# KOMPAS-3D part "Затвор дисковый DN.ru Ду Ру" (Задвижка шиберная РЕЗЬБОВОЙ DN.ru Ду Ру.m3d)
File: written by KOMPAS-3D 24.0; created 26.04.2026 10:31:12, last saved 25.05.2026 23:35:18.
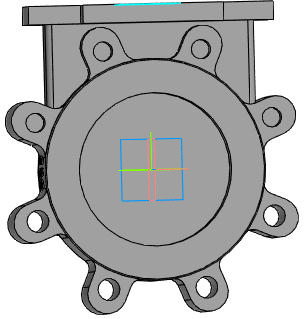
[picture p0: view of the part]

Document properties: Автор: R2D2; Полное имя файла: E:\Работа\Зайцев\GVKR1331M-1W-Fb-2P Задвижка шиберная с выдвижным штоком DN.ru Ду50-300 Ру16-10-6 с пневмоприводом\исходные материалы\DN125\Задвижка шиберная РЕЗЬБОВОЙ DN.ru Ду Ру.m3d

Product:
- Part/product: Затвор дисковый DN.ru Ду Ру
    Масса: 18.2
    Раздел спецификации: Прочие изделия
    Примечание: D050-23732

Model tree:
1. Смещенная плоскость:2
2. Диск
3. Корпус
4. Элемент выдавливания:3
     Расстояние 1 = 30
5. Элемент вращения:1
     Угол 1 = 360
6. Корпус штока
7. Элемент выдавливания:6  (with: Грань.Элемент вращения:1)
     Расстояние 1 = 135
8. Ушко  (with: Ребро.Элемент вращения:1)
9. Элемент выдавливания:5
10. Эскиз:1  (with: Ребро.Элемент выдавливания:5)
11. Элемент выдавливания:12
     Расстояние 1 = 28.5; Расстояние 2 = 28.5
12. Элемент выдавливания:13
13. Массив по концентрической сетке:1  (with: Элемент выдавливания:13, Эскиз:1, Элемент выдавливания:12, Элемент выдавливания:5)  (8 pattern instances)
     Шаг 2 = 360
14. Эскиз:2  (labels: Ребро.Элемент выдавливания:5.Экземпляр ( 1, 3 ); Ребро.Элемент выдавливания:5.Экземпляр ( 1, 6 ))
15. Элемент выдавливания:14
16. площадка  (with: Грань.Элемент выдавливания:6, Ребро.Элемент выдавливания:5)
17. Элемент выдавливания:15
     Расстояние 2 = 15
18. Скругление:10  (with: Ребро.Элемент выдавливания:6)
     Радиус = 5
19. Эскиз:4  (labels: Задвижка шиберная с выдвижным штоком DN.ru Ду50 Ру16; Затвор дисковый DN.ru Ду200 Ру16)
20. Элемент выдавливания:16  (with: Грань.Элемент вращения:1)
     Смещение 1 = 1
21. Эскиз:5  (labels: Задвижка шиберная DN.ru Ду50 Ру10; Затвор дисковый DN.ru Ду200 Ру16)
22. Элемент выдавливания:17  (with: Грань.Элемент вращения:1)
     Расстояние 1 = 91.4974; Смещение 1 = 1
23. Скругление:8  (with: Ребро.Элемент вращения:1)
     Радиус = 1
24. Скругление:11  (with: Ребро.Элемент выдавливания:16)
     Радиус = 10
25. Скругление:13  (with: Ребро.Элемент выдавливания:16)
     Радиус = 8

Expressions: 360/n; c-8-2*t; v1301/2; d/2+30; dd/2
Referenced files in E:\Работа\Зайцев\GVKR1331E-1W-Fb-2P Задвижка шиберная DN.ru Ду50-300 Ру16-10-6\исходные материалы\DN50\: GVKR1331E-1W-Fb-2P Задвижка шиберная с выдвижным штоком DN.ru Ду50 Ру16.a3d, GVKR1331E-1W-Fb-2P Задвижка шиберная DN.ru Ду50 Ру16.a3d
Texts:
  Угловой размер с обрывом
  GOST 26.020 Pr3
  var3D
  ширина затвора по металлу
  площадка под крепеж
  DN+10
  dk+20
  dk-10
  Плоскость ZY.Начало координат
